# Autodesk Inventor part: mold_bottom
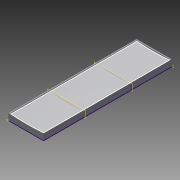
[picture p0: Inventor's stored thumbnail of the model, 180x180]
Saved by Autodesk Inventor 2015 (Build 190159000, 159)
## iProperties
Created: 2015-04
Part Number: mold_bottom
Material: Generic
Document SubType Name: Modeling
Designer: sungeun
Density: 1 g/cm^3
Appearance: Default
Author: sungeun
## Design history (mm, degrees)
sketch "Sketch1"
  geometry: L1 (300, 1100)-(0, 1100); L2 (0, 1100)-(0, 0); L3 (0, 0)-(300, 0); L4 (300, 0)-(300, 1100); L5 (300, 1100)-(0, 0); L6 (0, 1100)-(300, 0); 3 further points
  constraints: 12 end point, 2 midpoint, 2 parallel, 1 coincident, 1 horizontal, 1 horizontal alignment, 1 perpendicular, 1 vertical alignment
  dimensions: "d0" = 300 distance of L3.end L2.end; "d1" = 1100 distance of L2.end L1.end
extrude "Extrusion1" new body sketch "Sketch1" distance "d2" = 50; taper "d3" = 0 deg
sketch "Sketch2"
  geometry: L1 (300, -50)-(0, -50); L2 (300, -50)-(0, -50) reference; A1 r 2000 centre (150, -2044.367) between (300, -50) and (0, -50); 1 further point
  constraints: 2 end point, 2 point on circle, 1 centre point, 1 collinear
  dimensions: "d17" = 2000 radius of A1
sketch "Sketch3"
  geometry: L1 (0, 50)-(300, 50); L2 (300, 50)-(0, 50) reference; A1 r 2000 centre (150, 2044.367) between (0, 50) and (300, 50); 1 further point
  constraints: 2 end point, 2 point on circle, 1 centre point, 1 collinear
  dimensions: "d5" = 2000 radius of A1
workplane "Work Plane1"
workplane "Work Plane2"
sketch "Sketch5"
  geometry: L1 (0, 50)-(300, 50); L2 (300, 0)-(300, 50) reference; A1 r 700 centre (150, 733.74) between (0, 50) and (300, 50); 1 further point
  constraints: 2 end point, 2 point on circle, 1 centre point, 1 perpendicular
  dimensions: "d9" = 700 radius of A1
sketch "Sketch6"
  geometry: L1 (0, -50)-(300, -50); A1 r 1400 centre (150, -1441.941) between (300, -50) and (0, -50); 1 further point
  constraints: 2 end point, 2 point on circle, 1 centre point, 1 horizontal
  dimensions: "d10" = 1400 radius of A1
loft "Loft1" sketch "Sketch5", "Sketch6" dims "d11" = 0, "d12" = 90 deg, "d13" = 0, "d14" = 90 deg, "d15" = 0, "d16" = 90 deg, "d18" = 0, "d19" = 90 deg
sketch "Sketch7"
  geometry: L1 (0, 0)-(-300, 0); L2 (-300, 0)-(-300, 1100); L3 (-300, 1100)-(0, 1100); L4 (0, 1100)-(0, 0); 1 further point
  constraints: 8 end point, 2 parallel, 1 horizontal, 1 perpendicular
sketch "Sketch8"
  geometry: L1 (0, 0)-(-300, 0); L2 (-300, 0)-(-300, 1100); L3 (-300, 1100)-(0, 1100); L4 (0, 1100)-(0, 0); L5 (-290, 10)-(-10, 10); L6 (-10, 10)-(-10, 1090); L7 (-10, 1090)-(-290, 1090); L8 (-290, 1090)-(-290, 10)
  constraints: 16 end point, 4 parallel, 2 perpendicular, 1 horizontal, 3 other
  dimensions: "d20" = 10 distance between parallel lines of L1 L5
extrude "Extrusion2" join sketch "Sketch8" distance "d21" = 55; taper "d22" = 0 deg
body "Solid1"
